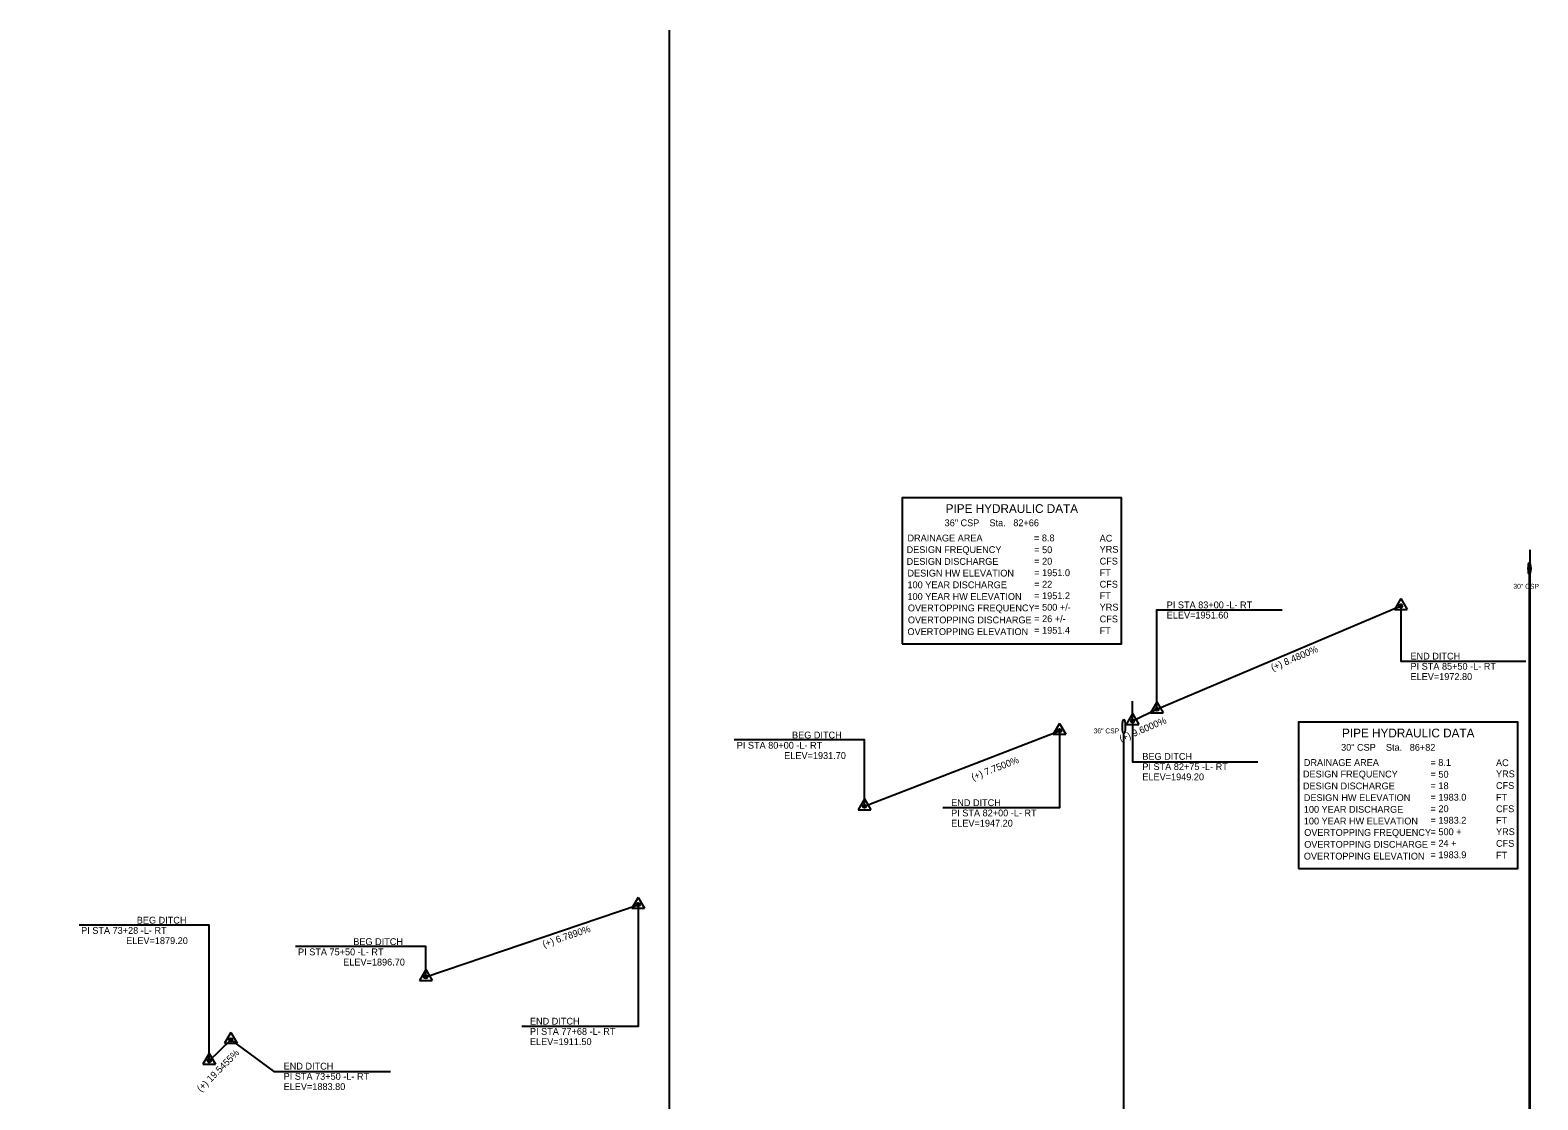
# Model space of a CAD drawing. Extents: x 1025306 to 1036906, y 638983 to 643947.
# Drawn here: x 1031450 to 1032996, y 641847 to 642944 of the extents above; entities that cross this region are included whole.
import ezdxf

# ---------------------------------------------------------------- set-up
doc = ezdxf.new("R2010")
doc.units = 0
for name, color, linetype in [('Default', 7, 'Continuous'), ('Prop PFL Cross Pipe CELL', 7, 'Continuous'), ('Prop PFL Cross Pipe Text CELL', 7, 'Continuous'), ('Prop PFL Pipe Hydraulic Data CELL', 7, 'Continuous'), ('Prop Vertical Profile Ditch Grade Right', 7, 'Continuous'), ('Prop Vertical Profile Ditch Grade Right Label', 7, 'Continuous'), ('Prop VPI Ditch Grade Right Label', 7, 'Continuous'), ('Scratch_Level_0', 7, 'Continuous'), ('Scratch_Level_1', 7, 'Continuous'), ('Scratch_Level_3', 7, 'Continuous')]:
    doc.layers.add(name, color=color, linetype=linetype)

msp = doc.modelspace()

# ---------------------------------------------------------------- linework, layer by layer
at = {"layer": 'Default'}
for p, q in [((1032855.6, 642360.9), (1032849.1, 642349.7)), ((1032855.6, 642360.9), (1032862.1, 642349.7)), ((1032849.1, 642349.7), (1032862.1, 642349.7)), ((1032605.6, 642254.9), (1032599.1, 642243.7)), ((1032605.6, 642254.9), (1032612.1, 642243.7)), ((1032505.6, 642232.9), (1032499.1, 642221.7)), ((1032505.6, 642232.9), (1032512.1, 642221.7)), ((1032580.6, 642242.9), (1032574.1, 642231.7)), ((1032574.1, 642231.7), (1032587.1, 642231.7)), ((1032580.6, 642242.9), (1032587.1, 642231.7)), ((1032599.1, 642243.7), (1032612.1, 642243.7)), ((1032499.1, 642221.7), (1032512.1, 642221.7)), ((1032305.6, 642155.4), (1032299.1, 642144.2)), ((1032305.6, 642155.4), (1032312.1, 642144.2)), ((1032299.1, 642144.2), (1032312.1, 642144.2)), ((1032073.6, 642054.4), (1032067.1, 642043.2)), ((1032073.6, 642054.4), (1032080.1, 642043.2)), ((1032067.1, 642043.2), (1032080.1, 642043.2)), ((1031855.6, 641980.4), (1031849.1, 641969.2)), ((1031849.1, 641969.2), (1031862.1, 641969.2)), ((1031855.6, 641980.4), (1031862.1, 641969.2)), ((1031655.6, 641915.9), (1031649.1, 641904.7)), ((1031655.6, 641915.9), (1031662.1, 641904.7)), ((1031633.6, 641894.4), (1031627.1, 641883.2)), ((1031633.6, 641894.4), (1031640.1, 641883.2)), ((1031649.1, 641904.7), (1031662.1, 641904.7)), ((1031627.1, 641883.2), (1031640.1, 641883.2))]:
    msp.add_line(p, q, dxfattribs=at)
for centre, radius in [((1032855.6, 642353.4), 1.75), ((1032855.6, 642353.4), 1.2), ((1032605.6, 642247.4), 1.75), ((1032605.6, 642247.4), 1.2), ((1032580.6, 642235.4), 1.75), ((1032580.6, 642235.4), 1.2), ((1032505.6, 642225.4), 1.75), ((1032505.6, 642225.4), 1.2), ((1032305.6, 642147.9), 1.75), ((1032305.6, 642147.9), 1.2), ((1032073.6, 642046.9), 1.75), ((1032073.6, 642046.9), 1.2), ((1031855.6, 641972.9), 1.75), ((1031855.6, 641972.9), 1.2), ((1031655.6, 641908.4), 1.75), ((1031655.6, 641908.4), 1.2), ((1031633.6, 641886.9), 1.75), ((1031633.6, 641886.9), 1.2)]:
    msp.add_circle(centre, radius, dxfattribs=at)
at = {"layer": 'Prop PFL Cross Pipe CELL'}
for centre, major_axis in [((1032987.6, 642391.8), (0, 6.25)), ((1032571.6, 642229.6), (0, 7.5))]:
    msp.add_ellipse(centre, major_axis=major_axis, ratio=0.2, dxfattribs=at)
at = {"layer": 'Prop PFL Pipe Hydraulic Data CELL'}
for points in [[(1032344.1, 642314.4), (1032569.1, 642314.4), (1032569.1, 642464.4), (1032344.1, 642464.4)], [(1032750.6, 642084.1), (1032975.6, 642084.1), (1032975.6, 642234.1), (1032750.6, 642234.1)]]:
    msp.add_lwpolyline(points, close=True, dxfattribs=at)
at = {"layer": 'Prop Vertical Profile Ditch Grade Right'}
for p, q in [((1032305.6, 642147.9), (1032505.6, 642225.4)), ((1031855.6, 641972.9), (1032073.6, 642046.9)), ((1031633.6, 641886.9), (1031655.6, 641908.4))]:
    msp.add_line(p, q, dxfattribs=at)
msp.add_lwpolyline([(1032580.6, 642235.4), (1032605.6, 642247.4), (1032855.6, 642353.4)], dxfattribs=at)
at = {"layer": 'Prop VPI Ditch Grade Right Label'}
for points in [[(1032605.6, 642247.4), (1032605.6, 642349.4), (1032733.9, 642349.4)], [(1032855.6, 642353.4), (1032855.6, 642296.7), (1032983.9, 642296.7)], [(1032580.6, 642235.4), (1032580.6, 642193.6), (1032708.9, 642193.6)], [(1032305.6, 642147.9), (1032305.6, 642215.9), (1032172.1, 642215.9)], [(1032505.6, 642225.4), (1032505.6, 642146.2), (1032386.1, 642146.2)], [(1032073.6, 642046.9), (1032073.6, 641922.1), (1031954.1, 641922.1)], [(1031633.6, 641886.9), (1031633.6, 642026), (1031500.1, 642026)], [(1031855.6, 641972.9), (1031855.6, 642004), (1031722.1, 642004)], [(1031655.6, 641908.4), (1031699.9, 641875.9), (1031819.5, 641875.9)]]:
    msp.add_lwpolyline(points, dxfattribs=at)
for centre in [(1032855.6, 642353.4), (1032580.6, 642235.4), (1032505.6, 642225.4), (1032305.6, 642147.9), (1032073.6, 642046.9), (1031855.6, 641972.9), (1031655.6, 641908.4), (1031633.6, 641886.9)]:
    msp.add_circle(centre, 0.5, dxfattribs=at)
at = {"layer": 'Scratch_Level_0'}
msp.add_lwpolyline([(1025305.6, 639889.4), (1032988.4, 639889.4), (1032988.4, 642410.8)], dxfattribs=at)
at = {"layer": 'Scratch_Level_1'}
msp.add_line((1032580.6, 642235.4), (1032580.6, 642255.7), dxfattribs=at)
for points in [[(1025305.6, 639889.4), (1032987.6, 639889.4), (1032987.6, 642398)], [(1025305.6, 639889.4), (1032571.6, 639889.4), (1032571.6, 642222.1)]]:
    msp.add_lwpolyline(points, dxfattribs=at)
at = {"layer": 'Scratch_Level_3'}
msp.add_line((1032105.6, 639889.4), (1032105.6, 642944), dxfattribs=at)

# ---------------------------------------------------------------- texts
at = {"layer": 'Prop PFL Cross Pipe Text CELL'}
for s, p in [('30" CSP', (1032971.1, 642371)), ('36" CSP', (1032540.6, 642222.7))]:
    msp.add_text(s, height=5, dxfattribs=at).set_placement(p)
at = {"layer": 'Prop PFL Pipe Hydraulic Data CELL'}
for s, height, p in [('PIPE HYDRAULIC DATA', 9, (1032388.9, 642448.7)), ('  36" CSP    Sta.   82+66  ', 7, (1032382.6, 642435.1)), ('DRAINAGE AREA', 7, (1032349.7, 642419.5)), ('= 8.8 ', 7, (1032479.5, 642419.6)), ('AC', 7, (1032546.8, 642419.3)), ('DESIGN FREQUENCY', 7, (1032348.8, 642407.6)), ('DESIGN DISCHARGE', 7, (1032348.8, 642395.5)), ('= 50 ', 7, (1032479.7, 642407.5)), ('= 20 ', 7, (1032479.7, 642395.7)), ('YRS', 7, (1032546.8, 642407.9)), ('CFS', 7, (1032546.8, 642395.8)), ('DESIGN HW ELEVATION', 7, (1032349.7, 642383.5)), ('= 1951.0', 7, (1032479.7, 642383.9)), ('FT', 7, (1032546.8, 642383.9)), ('100 YEAR DISCHARGE', 7, (1032349.7, 642371.5)), ('= 22 ', 7, (1032479.7, 642372.1)), ('CFS', 7, (1032546.8, 642372.1)), ('100 YEAR HW ELEVATION', 7, (1032349.7, 642359.5)), ('OVERTOPPING FREQUENCY', 7, (1032350.1, 642347.8)), ('= 1951.2', 7, (1032479.7, 642360.3)), ('= 500 +/-', 7, (1032479.7, 642348.5)), ('YRS', 7, (1032546.8, 642348.6)), ('FT', 7, (1032546.8, 642360.3)), ('OVERTOPPING DISCHARGE', 7, (1032350.1, 642335.5)), ('= 26 +/-', 7, (1032479.7, 642336.7)), ('CFS', 7, (1032546.8, 642336.5)), ('OVERTOPPING ELEVATION', 7, (1032349.7, 642323.5)), ('= 1951.4', 7, (1032479.7, 642324.9)), ('FT', 7, (1032546.8, 642324.5)), ('PIPE HYDRAULIC DATA', 9, (1032795.4, 642218.5)), ('  30" CSP    Sta.   86+82  ', 7, (1032789.2, 642204.8)), ('DESIGN FREQUENCY', 7, (1032755.3, 642177.4)), ('DRAINAGE AREA', 7, (1032756.2, 642189.2)), ('= 8.1 ', 7, (1032886, 642189.3)), ('= 50 ', 7, (1032886.2, 642177.2)), ('AC', 7, (1032953.3, 642189)), ('YRS', 7, (1032953.3, 642177.6)), ('DESIGN DISCHARGE', 7, (1032755.3, 642165.2)), ('= 18 ', 7, (1032886.2, 642165.4)), ('CFS', 7, (1032953.3, 642165.6)), ('DESIGN HW ELEVATION', 7, (1032756.2, 642153.2)), ('= 1983.0', 7, (1032886.2, 642153.6)), ('FT', 7, (1032953.3, 642153.6)), ('100 YEAR DISCHARGE', 7, (1032756.2, 642141.2)), ('= 20 ', 7, (1032886.2, 642141.8)), ('= 1983.2', 7, (1032886.2, 642130)), ('CFS', 7, (1032953.3, 642141.8)), ('100 YEAR HW ELEVATION', 7, (1032756.2, 642129.2)), ('OVERTOPPING FREQUENCY', 7, (1032756.6, 642117.5)), ('= 500 +  ', 7, (1032886.2, 642118.2)), ('YRS', 7, (1032953.3, 642118.3)), ('FT', 7, (1032953.3, 642130)), ('OVERTOPPING DISCHARGE', 7, (1032756.6, 642105.3)), ('= 24 +  ', 7, (1032886.2, 642106.4)), ('CFS', 7, (1032953.3, 642106.3)), ('OVERTOPPING ELEVATION', 7, (1032756.2, 642093.2)), ('= 1983.9', 7, (1032886.2, 642094.6)), ('FT', 7, (1032953.3, 642094.2))]:
    msp.add_text(s, height=height, dxfattribs=at).set_placement(p)
at = {"layer": 'Prop Vertical Profile Ditch Grade Right Label'}
for s, rotation, p in [('(+) 8.4800%', 22.9593, (1032724.2, 642286.5)), ('(+) 9.6000%', 22.9593, (1032568.8, 642213.4)), ('(+) 7.7500%', 21.1813, (1032416.8, 642174.2)), ('(+) 6.7890%', 18.7498, (1031976.8, 642002.8)), ('(+) 19.5455%', 45, (1031625.1, 641854.3))]:
    msp.add_text(s, height=7, rotation=rotation, dxfattribs=at).set_placement(p)
at = {"layer": 'Prop VPI Ditch Grade Right Label'}
for s, p in [('PI STA 83+00 -L- RT', (1032615.6, 642350.9)), ('ELEV=1951.60', (1032615.6, 642340.4)), ('END DITCH', (1032865.6, 642298.4)), ('PI STA 85+50 -L- RT', (1032865.6, 642287.9)), ('ELEV=1972.80', (1032865.6, 642277.4)), ('BEG DITCH', (1032231.3, 642217.4)), ('PI STA 80+00 -L- RT', (1032174.6, 642206.9)), ('ELEV=1931.70', (1032223.3, 642196.4)), ('BEG DITCH', (1032590.6, 642195.5)), ('PI STA 82+75 -L- RT', (1032590.6, 642185)), ('ELEV=1949.20', (1032590.6, 642174.5)), ('END DITCH', (1032394.5, 642148)), ('PI STA 82+00 -L- RT', (1032394.5, 642137.5)), ('ELEV=1947.20', (1032394.5, 642127)), ('BEG DITCH', (1031559.3, 642027.5)), ('PI STA 73+28 -L- RT', (1031502.2, 642017)), ('ELEV=1879.20', (1031548.4, 642006.5)), ('PI STA 75+50 -L- RT', (1031724.7, 641995)), ('BEG DITCH', (1031781.3, 642005.5)), ('ELEV=1896.70', (1031771, 641984.5)), ('END DITCH', (1031962.5, 641923.9)), ('PI STA 77+68 -L- RT', (1031962.5, 641913.4)), ('ELEV=1911.50', (1031962.5, 641902.9)), ('END DITCH', (1031709.9, 641877.8)), ('PI STA 73+50 -L- RT', (1031709.9, 641867.3)), ('ELEV=1883.80', (1031709.9, 641856.8))]:
    msp.add_text(s, height=7, dxfattribs=at).set_placement(p)

doc.saveas('drawing.dxf')
